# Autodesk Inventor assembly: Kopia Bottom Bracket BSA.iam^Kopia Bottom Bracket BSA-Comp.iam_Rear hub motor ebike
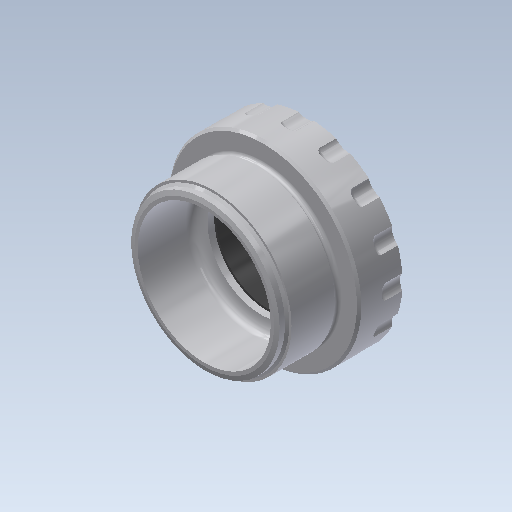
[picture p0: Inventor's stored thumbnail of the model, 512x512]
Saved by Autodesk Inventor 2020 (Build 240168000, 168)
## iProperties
Created: 2017-11
Part Number: Kopia Bottom Bracket BSA.iam^Kopia Bottom Bracket BSA-Comp.iam_Rear hub motor ebike
Material: Ogólny
Document SubType Name: Assembly
Designer: Tomasz
Sending System: SolidWorks 2017
Last Author: Tomasz
Last Saved: 2017-11-19
Author: Tomasz
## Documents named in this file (5)
- C:\Users\bruno\Documents\1-Cours-2020-21\1STI2D-2020-21\IT\6. Antivol\Inventor-Antivol\INVENTOR 2018_Steel Hardtail B+\Kopia Bottom Bracket BSA.iam^Kopia Bottom Bracket BSA-Comp.iam_Rear hub motor ebike.iam
- C:\Users\Tomasz\Desktop\Rear Hub Motor Ebike\Kopia radial ball bearing_68_skf_SKF - 61805 - 22,DE,NC,22_68.ipt^Kopia Bottom Bracket BSA.iam_Kopia Bottom Bracket BSA-Comp.iam_Rear hub motor ebike.ipt
- C:\Users\bruno\Documents\1-Cours-2020-21\1STI2D-2020-21\IT\6. Antivol\Inventor-Antivol\INVENTOR 2018_Steel Hardtail B+\Kopia Parapolvere Cuscinetto.ipt^Kopia Bottom Bracket BSA.iam_Kopia Bottom Bracket BSA-Comp.iam_Rear hub motor ebike.ipt
- C:\Users\bruno\Documents\1-Cours-2020-21\1STI2D-2020-21\IT\6. Antivol\Inventor-Antivol\INVENTOR 2018_Steel Hardtail B+\Kopia Parapolvere.ipt^Kopia Bottom Bracket BSA.iam_Kopia Bottom Bracket BSA-Comp.iam_Rear hub motor ebike.ipt
- C:\Users\bruno\Documents\1-Cours-2020-21\1STI2D-2020-21\IT\6. Antivol\Inventor-Antivol\INVENTOR 2018_Steel Hardtail B+\Kopia Calotta MC BSA.ipt^Kopia Bottom Bracket BSA.iam_Kopia Bottom Bracket BSA-Comp.iam_Rear hub motor ebike.ipt
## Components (4 placed, 4 different names)
1. Kopia radial ball bearing_68_skf_SKF - 61805 - 22,DE,NC,22_68.ipt^Kopia Bottom Bracket BSA.iam_Kopia Bottom Bracket BSA-Comp.iam_Rear hub motor ebike:1
2. Kopia Parapolvere Cuscinetto.ipt^Kopia Bottom Bracket BSA.iam_Kopia Bottom Bracket BSA-Comp.iam_Rear hub motor ebike:1
3. Kopia Parapolvere.ipt^Kopia Bottom Bracket BSA.iam_Kopia Bottom Bracket BSA-Comp.iam_Rear hub motor ebike:1
4. Kopia Calotta MC BSA.ipt^Kopia Bottom Bracket BSA.iam_Kopia Bottom Bracket BSA-Comp.iam_Rear hub motor ebike:1
